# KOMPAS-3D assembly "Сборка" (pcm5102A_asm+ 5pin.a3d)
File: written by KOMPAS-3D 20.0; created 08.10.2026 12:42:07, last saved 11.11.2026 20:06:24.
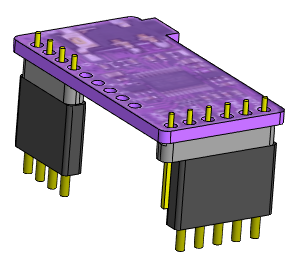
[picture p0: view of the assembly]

Document properties: Полное имя файла: D:\myProjects\Progect_esp32\box_compas\цап ацп\pcm5102A_asm+ 5pin.a3d

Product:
- Part/product: Сборка
    Масса: 0.0102229
  - Component [detail]: Деталь  | Масса: 0.00125697; source file: ..\разъемы\pbs_4.m3d
  - Component [detail]: Деталь  | Масса: 0.000505328; source file: ..\разъемы\pls_4.m3d
  - Component [detail]: Деталь  | Масса: 0.00613645; source file: pcm5102A.m3d
  - Component [detail]: Деталь  | Масса: 0.000766031; source file: ..\разъемы\pls_6.m3d
  - Component [detail]: Деталь  | Масса: 0.0015581; source file: ..\разъемы\pbs_5.m3d

Referenced files in D:\myProjects\Progect_esp32\box_compas\цап ацп\: pcm5102A.m3d
Referenced files in D:\myProjects\Progect_esp32\box_compas\разъемы\: pls_6.m3d, pls_4.m3d, pbs_4.m3d, pbs_5.m3d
